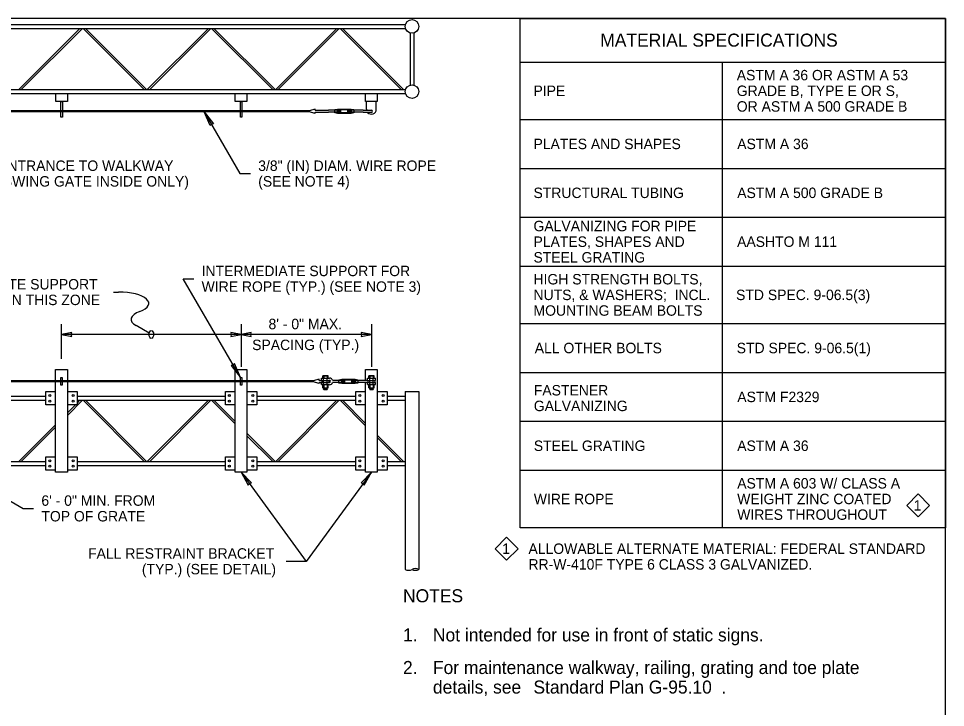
# Model space of a CAD drawing. Extents: x 99862 to 103151, y 100000 to 105076.
# Drawn here: x 101730 to 103151, y 101019 to 102076 of the extents above; entities that cross this region are included whole.
import ezdxf

# ---------------------------------------------------------------- set-up
doc = ezdxf.new("R2010")
doc.units = 0
for name, color, linetype in [('Level 1', 7, 'Continuous'), ('Level 11', 7, 'Continuous'), ('Level 14', 7, 'Continuous'), ('Level 15', 7, 'Continuous'), ('Level 18', 7, 'Continuous'), ('Level 20', 7, 'Continuous'), ('Level 23', 7, 'Continuous'), ('Level 3', 7, 'Continuous'), ('Level 4', 7, 'Continuous'), ('Level 60', 7, 'Continuous'), ('Level 7', 7, 'Continuous')]:
    doc.layers.add(name, color=color, linetype=linetype)

msp = doc.modelspace()

# ---------------------------------------------------------------- linework, layer by layer
at = {"layer": 'Level 1'}
msp.add_lwpolyline([(99862, 99999.5), (103151, 99999.5), (103151, 102075.5), (99862, 102075.5)], close=True, dxfattribs=at)
at = {"layer": 'Level 11'}
for p, q in [((102263.4, 101936.3), (102263.4, 101948.3)), ((102278.3, 101936.3), (102278.3, 101948.3)), ((102167.4, 101934.2), (101540, 101934.2)), ((102167.4, 101932.5), (101540, 101932.5)), ((102175.1, 101934.2), (102167.4, 101934.2)), ((102175.1, 101932.5), (102167.4, 101932.5)), ((102184.4, 101936.7), (102175.1, 101934.2)), ((102175.1, 101934.2), (102175.1, 101932.5)), ((102184.4, 101930), (102175.1, 101932.5)), ((102184.4, 101935), (102184.4, 101936.7)), ((102184.4, 101935), (102205, 101935)), ((102184.4, 101931.7), (102205, 101931.7)), ((102184.4, 101930), (102184.4, 101931.7)), ((102214.8, 101935), (102205, 101935)), ((102214.8, 101931.7), (102205, 101931.7)), ((102219, 101935), (102214.8, 101935)), ((102219, 101931.7), (102214.8, 101931.7)), ((102219, 101935.8), (102239.6, 101935.8)), ((102219, 101930.9), (102219, 101935.8)), ((102219, 101935), (102224, 101935)), ((102219, 101931.7), (102224, 101931.7)), ((102239.6, 101930.9), (102219, 101930.9)), ((102219.8, 101932.5), (102219.8, 101934.2)), ((102220.7, 101931.7), (102220.7, 101935)), ((102221.5, 101932.5), (102221.5, 101934.2)), ((102222.3, 101931.7), (102222.3, 101935)), ((102223.1, 101932.5), (102223.1, 101934.2)), ((102224, 101931.7), (102224, 101935)), ((102239.6, 101935), (102234.6, 101935)), ((102234.6, 101931.7), (102234.6, 101935)), ((102239.6, 101931.7), (102234.6, 101931.7)), ((102235.4, 101932.5), (102235.4, 101934.2)), ((102236.3, 101931.7), (102236.3, 101935)), ((102237.1, 101932.5), (102237.1, 101934.2)), ((102237.9, 101931.7), (102237.9, 101935)), ((102238.8, 101932.5), (102238.8, 101934.2)), ((102239.6, 101935.8), (102239.6, 101930.9)), ((102243.8, 101935), (102239.6, 101935)), ((102243.8, 101931.7), (102239.6, 101931.7)), ((102258.3, 101935), (102243.8, 101935)), ((102258.3, 101931.7), (102243.8, 101931.7)), ((102258.3, 101935), (102270.8, 101935)), ((102258.3, 101931.7), (102270.8, 101931.7))]:
    msp.add_line(p, q, dxfattribs=at)
for points in [[(101794.7, 101948.3), (101797, 101948.3), (101797, 101924.3), (101794.7, 101924.3)], [(102069.8, 101948.3), (102072, 101948.3), (102072, 101924.3), (102069.8, 101924.3)], [(102214.8, 101935.8), (102218.9, 101936.7), (102239.7, 101936.7), (102243.8, 101935.8), (102243.8, 101930.9), (102239.7, 101930), (102218.9, 101930), (102214.8, 101930.9)], [(101794.4, 101525), (101796.7, 101525), (101796.7, 101513), (101794.4, 101513)], [(102069.8, 101525), (102072, 101525), (102072, 101513), (102069.8, 101513)]]:
    msp.add_lwpolyline(points, close=True, dxfattribs=at)
for centre, radius, start, end in [((102270.8, 101936.3), 7.45, 180, 190.3619), ((102270.8, 101936.3), 7.45, 218.7191, 0), ((102270.8, 101933.3), 1.66, 270, 90)]:
    msp.add_arc(centre, radius, start, end, dxfattribs=at)
at = {"layer": 'Level 14'}
msp.add_line((101875.1, 101656), (101883.1, 101656), dxfattribs=at)
for centre, start_param, end_param in [((101883.1, 101638.6), 2.356226, 4.712389), ((101948.7, 101614), 5.497747, 6.859209)]:
    msp.add_ellipse(centre, major_axis=(-46.4, 0), ratio=0.375, start_param=start_param, end_param=end_param, dxfattribs=at)
at = {"layer": 'Level 15'}
for p, q in [((102014.5, 101932.5), (102069.2, 101837.8)), ((102069.2, 101837.8), (102085.2, 101837.8)), ((102069.8, 101525), (101982.3, 101676.4)), ((101982.3, 101676.4), (101998.3, 101676.4)), ((101795.6, 101553.5), (101795.6, 101607)), ((101929.9, 101592.9), (101909.8, 101604.5)), ((102070.9, 101607), (102070.9, 101541.5)), ((102270.8, 101607), (102270.8, 101541.5)), ((102070.9, 101591), (101795.6, 101591)), ((102270.8, 101591), (102070.9, 101591)), ((102070.9, 101380), (102170.9, 101243)), ((102270.8, 101380), (102170.9, 101243)), ((101659.5, 101368.7), (101736.7, 101324.2)), ((101736.7, 101324.2), (101752.7, 101324.2)), ((102170.9, 101243), (102140.2, 101243))]:
    msp.add_line(p, q, dxfattribs=at)
for points in [[(102014.5, 101932.5), (102028.5, 101914.2), (102025.4, 101913.7), (102023.3, 101911.2)], [(101795.6, 101591), (101811.3, 101587.9), (101810.6, 101591), (101811.3, 101594.1)], [(102070.9, 101591), (102055.2, 101594.1), (102055.9, 101591), (102055.2, 101587.9)], [(102070.9, 101591), (102086.6, 101587.9), (102085.9, 101591), (102086.6, 101594.1)], [(102070.9, 101591), (102086.6, 101587.9), (102085.9, 101591), (102086.6, 101594.1)], [(102270.8, 101591), (102255.1, 101594.1), (102255.8, 101591), (102255.1, 101587.9)], [(102069.8, 101525), (102060.9, 101546.3), (102058.9, 101543.8), (102055.8, 101543.3)], [(102070.9, 101380), (102081.9, 101359.8), (102083.7, 101362.4), (102086.8, 101363.3)], [(102270.8, 101380), (102255, 101363.3), (102258, 101362.4), (102259.8, 101359.8)]]:
    msp.add_lwpolyline(points, close=True, dxfattribs=at)
for centre, start, end in [((102327.8, 101239.7), 240, 300), ((102338.2, 101221.7), 60, 120), ((102338.2, 101239.7), 240, 300)]:
    msp.add_arc(centre, 10.4, start, end, dxfattribs=at)
msp.add_ellipse((101933.2, 101591), major_axis=(0, 6), ratio=0.57735, dxfattribs=at)
at = {"layer": 'Level 18'}
for points in [[(101786.6, 101519.8), (101786.6, 101537), (101804.6, 101537), (101804.6, 101519.8)], [(102061.9, 101519.8), (102061.9, 101537), (102079.9, 101537), (102079.9, 101519.8)], [(102279.8, 101537), (102279.8, 101380), (102261.8, 101380), (102261.8, 101517.3)], [(102261.8, 101520.6), (102261.8, 101537), (102279.8, 101537), (102279.8, 101537)], [(101804.6, 101518.2), (101804.6, 101380), (101786.6, 101380), (101786.6, 101518.2)], [(102079.9, 101518.2), (102079.9, 101380), (102061.9, 101380), (102061.9, 101518.2)], [(101786.6, 101482.8), (101771.6, 101482.8), (101771.6, 101503.3), (101786.6, 101503.3)], [(101804.6, 101503.3), (101819.6, 101503.3), (101819.6, 101482.8), (101804.6, 101482.8)], [(102061.9, 101482.8), (102046.9, 101482.8), (102046.9, 101503.3), (102061.9, 101503.3)], [(102079.9, 101503.3), (102094.9, 101503.3), (102094.9, 101482.8), (102079.9, 101482.8)], [(102261.8, 101482.8), (102246.8, 101482.8), (102246.8, 101503.3), (102261.8, 101503.3)], [(102279.8, 101503.3), (102294.8, 101503.3), (102294.8, 101482.8), (102279.8, 101482.8)], [(101786.6, 101382.8), (101771.6, 101382.8), (101771.6, 101403.3), (101786.6, 101403.3)], [(101804.6, 101403.3), (101819.6, 101403.3), (101819.6, 101382.8), (101804.6, 101382.8)], [(102061.9, 101382.8), (102046.9, 101382.8), (102046.9, 101403.3), (102061.9, 101403.3)], [(102079.9, 101403.3), (102094.9, 101403.3), (102094.9, 101382.8), (102079.9, 101382.8)], [(102261.8, 101382.8), (102246.8, 101382.8), (102246.8, 101403.3), (102261.8, 101403.3)], [(102279.8, 101403.3), (102294.8, 101403.3), (102294.8, 101382.8), (102279.8, 101382.8)]]:
    msp.add_lwpolyline(points, dxfattribs=at)
for centre in [(101777.6, 101497.3), (101813.6, 101497.3), (102052.9, 101497.3), (102088.9, 101497.3), (102252.8, 101497.3), (102288.8, 101497.3), (101777.6, 101488.8), (101813.6, 101488.8), (102052.9, 101488.8), (102088.9, 101488.8), (102252.8, 101488.8), (102288.8, 101488.8), (101777.6, 101397.3), (101813.6, 101397.3), (102052.9, 101397.3), (102088.9, 101397.3), (102252.8, 101397.3), (102288.8, 101397.3), (101777.6, 101388.8), (101813.6, 101388.8), (102052.9, 101388.8), (102088.9, 101388.8), (102252.8, 101388.8), (102288.8, 101388.8)]:
    msp.add_circle(centre, 1.5, dxfattribs=at)
at = {"layer": 'Level 20'}
for points in [[(103109.1, 101346.3), (103126.7, 101328.8), (103109.1, 101311.2), (103091.6, 101328.8)], [(102478, 101280), (102495.6, 101262.4), (102478, 101244.9), (102460.5, 101262.4)]]:
    msp.add_lwpolyline(points, close=True, dxfattribs=at)
at = {"layer": 'Level 23'}
for points in [[(101786.8, 101960.3), (101804.8, 101960.3), (101804.8, 101948.3), (101786.8, 101948.3)], [(102061.9, 101960.3), (102079.9, 101960.3), (102079.9, 101948.3), (102061.9, 101948.3)], [(102261.8, 101960.3), (102279.8, 101960.3), (102279.8, 101948.3), (102261.8, 101948.3)]]:
    msp.add_lwpolyline(points, close=True, dxfattribs=at)
at = {"layer": 'Level 3'}
for p, q in [((102498.7, 102008.8), (103151, 102008.8)), ((102808.8, 102008.8), (102808.8, 101294.6)), ((102498.7, 101920.7), (103151, 101920.7)), ((102498.7, 101845.7), (103151, 101845.7)), ((102498.7, 101770.8), (103151, 101770.8)), ((102498.7, 101695.8), (103151, 101695.8)), ((102498.7, 101607.7), (103151, 101607.7)), ((102498.7, 101532.7), (103151, 101532.7)), ((102498.7, 101457.8), (103151, 101457.8)), ((102498.7, 101382.8), (103151, 101382.8))]:
    msp.add_line(p, q, dxfattribs=at)
msp.add_lwpolyline([(102498.7, 102075.5), (103151, 102075.5), (103151, 101294.6), (102498.7, 101294.6)], close=True, dxfattribs=at)
at = {"layer": 'Level 4'}
for p, q in [((102196.2, 101524), (102196.2, 101527.4)), ((102197, 101527.7), (102203.5, 101527.7)), ((102197.9, 101527.4), (102197.9, 101524)), ((102202.7, 101527.4), (102202.7, 101524)), ((102204.4, 101524), (102204.4, 101527.4)), ((102266.7, 101524), (102266.7, 101527.4)), ((102267.6, 101527.7), (102274.1, 101527.7)), ((102268.5, 101527.4), (102268.5, 101524)), ((102273.2, 101527.4), (102273.2, 101524)), ((102274.9, 101524), (102274.9, 101527.4)), ((102173.7, 101519.8), (101534.3, 101519.8)), ((102173.7, 101518.2), (101534.3, 101518.2)), ((102181.4, 101519.8), (102173.7, 101519.8)), ((102181.4, 101518.2), (102173.7, 101518.2)), ((102190.7, 101522.3), (102181.4, 101519.8)), ((102181.4, 101519.8), (102181.4, 101518.2)), ((102190.7, 101515.7), (102181.4, 101518.2)), ((102190.7, 101520.6), (102190.7, 101522.3)), ((102190.7, 101520.6), (102206.5, 101520.6)), ((102190.7, 101517.3), (102206.5, 101517.3)), ((102190.7, 101515.7), (102190.7, 101517.3)), ((102194, 101524), (102206.5, 101524)), ((102194, 101520.6), (102194, 101524)), ((102194, 101514), (102194, 101517.3)), ((102194, 101514), (102206.5, 101514)), ((102196.2, 101514), (102204.4, 101514)), ((102196.2, 101509.2), (102196.2, 101514)), ((102197.5, 101514), (102197.5, 101524)), ((102197.9, 101514), (102197.9, 101509.2)), ((102202.7, 101514), (102202.7, 101509.2)), ((102203, 101514), (102203, 101524)), ((102204.4, 101509.2), (102204.4, 101514)), ((102221, 101520.6), (102211.3, 101520.6)), ((102221, 101517.3), (102211.3, 101517.3)), ((102225.3, 101520.6), (102221, 101520.6)), ((102225.3, 101517.3), (102221, 101517.3)), ((102225.3, 101521.5), (102245.8, 101521.5)), ((102225.3, 101516.5), (102225.3, 101521.5)), ((102225.3, 101520.6), (102230.2, 101520.6)), ((102225.3, 101517.3), (102230.2, 101517.3)), ((102245.8, 101516.5), (102225.3, 101516.5)), ((102226.1, 101518.2), (102226.1, 101519.8)), ((102226.9, 101517.3), (102226.9, 101520.6)), ((102227.8, 101518.2), (102227.8, 101519.8)), ((102228.6, 101517.3), (102228.6, 101520.6)), ((102229.4, 101518.2), (102229.4, 101519.8)), ((102230.2, 101517.3), (102230.2, 101520.6)), ((102245.8, 101520.6), (102240.9, 101520.6)), ((102240.9, 101517.3), (102240.9, 101520.6)), ((102245.8, 101517.3), (102240.9, 101517.3)), ((102241.7, 101518.2), (102241.7, 101519.8)), ((102242.5, 101517.3), (102242.5, 101520.6)), ((102243.4, 101518.2), (102243.4, 101519.8)), ((102244.2, 101517.3), (102244.2, 101520.6)), ((102245, 101518.2), (102245, 101519.8)), ((102245.8, 101521.5), (102245.8, 101516.5)), ((102250.1, 101520.6), (102245.8, 101520.6)), ((102250.1, 101517.3), (102245.8, 101517.3)), ((102264.6, 101520.6), (102250.1, 101520.6)), ((102264.6, 101517.3), (102250.1, 101517.3)), ((102264.6, 101524), (102277.1, 101524)), ((102264.6, 101520.6), (102264.6, 101524)), ((102264.6, 101520.6), (102277.1, 101520.6)), ((102264.6, 101517.3), (102277.1, 101517.3)), ((102264.6, 101514), (102264.6, 101517.3)), ((102264.6, 101514), (102277.1, 101514)), ((102266.7, 101514), (102274.9, 101514)), ((102266.7, 101509.2), (102266.7, 101514)), ((102268.1, 101514), (102268.1, 101524)), ((102268.5, 101514), (102268.5, 101509.2)), ((102273.2, 101514), (102273.2, 101509.2)), ((102273.6, 101514), (102273.6, 101524)), ((102274.9, 101509.2), (102274.9, 101514)), ((102277.1, 101520.6), (102277.1, 101524)), ((102277.1, 101514), (102277.1, 101517.3)), ((102197, 101508.9), (102203.5, 101508.9)), ((102197.5, 101506.9), (102197.5, 101508.9)), ((102197.5, 101507.9), (102203, 101507.9)), ((102197.5, 101506.9), (102203, 101506.9)), ((102197.5, 101506.9), (102197.8, 101506.4)), ((102197.8, 101506.4), (102202.7, 101506.4)), ((102198.4, 101508.4), (102202.2, 101508.4)), ((102198.4, 101507.4), (102202.2, 101507.4)), ((102203, 101506.9), (102202.7, 101506.4)), ((102203, 101506.9), (102203, 101508.9)), ((102267.6, 101508.9), (102274.1, 101508.9)), ((102268.1, 101506.9), (102268.1, 101508.9)), ((102268.1, 101507.9), (102273.6, 101507.9)), ((102268.1, 101506.9), (102273.6, 101506.9)), ((102268.1, 101506.9), (102268.4, 101506.4)), ((102268.4, 101506.4), (102273.3, 101506.4)), ((102268.9, 101508.4), (102272.7, 101508.4)), ((102268.9, 101507.4), (102272.7, 101507.4)), ((102273.6, 101506.9), (102273.3, 101506.4)), ((102273.6, 101506.9), (102273.6, 101508.9))]:
    msp.add_line(p, q, dxfattribs=at)
msp.add_lwpolyline([(102221, 101521.5), (102225.2, 101522.3), (102245.9, 101522.3), (102250.1, 101521.5), (102250.1, 101516.5), (102245.9, 101515.7), (102225.2, 101515.7), (102221, 101516.5)], close=True, dxfattribs=at)
for centre, radius, start, end in [((102197, 101526.2), 1.5, 54.7199, 125.2801), ((102200.3, 101517.3), 10.3, 76.7504, 103.2496), ((102203.5, 101526.2), 1.5, 54.7199, 125.2801), ((102267.6, 101526.2), 1.5, 54.7199, 125.2801), ((102270.8, 101517.3), 10.3, 76.7504, 103.2496), ((102274.1, 101526.2), 1.5, 54.7199, 125.2801), ((102196.9, 101519), 2.22, 131.7358, 228.2642), ((102203.7, 101519), 2.22, 311.7358, 47.4328), ((102206.5, 101519), 5.03, 19.2502, 90), ((102206.5, 101519), 1.66, 270, 90), ((102206.5, 101519), 5.03, 270, 340.7483), ((102267.4, 101519), 2.22, 131.7358, 228.2642), ((102274.2, 101519), 2.22, 311.7358, 48.2642), ((102197, 101510.4), 1.5, 234.7199, 305.2801), ((102200.3, 101519.2), 10.3, 256.7504, 283.2496), ((102203.5, 101510.4), 1.5, 234.7199, 305.2801), ((102267.6, 101510.4), 1.5, 234.7199, 305.2801), ((102270.8, 101519.2), 10.3, 256.7504, 283.2496), ((102274.1, 101510.4), 1.5, 234.7199, 305.2801)]:
    msp.add_arc(centre, radius, start, end, dxfattribs=at)
at = {"layer": 'Level 60'}
msp.add_line((103151, 102075.5), (103151, 102075.5), dxfattribs=at)
at = {"layer": 'Level 7'}
for p, q in [((100622.1, 102066.6), (102322.6, 102066.6)), ((100622.1, 102060.3), (102322.6, 102060.3)), ((101823.9, 102060.3), (101730.2, 101966.6)), ((101827.6, 102060.3), (101733.9, 101966.6)), ((101828.7, 102060.3), (101922.4, 101966.6)), ((101832.3, 102060.3), (101926.1, 101966.6)), ((102020.9, 102060.3), (101927.1, 101966.6)), ((102024.6, 102060.3), (101930.8, 101966.6)), ((102025.6, 102060.3), (102119.4, 101966.6)), ((102029.3, 102060.3), (102123, 101966.6)), ((102217.8, 102060.3), (102124.1, 101966.6)), ((102221.5, 102060.3), (102127.8, 101966.6)), ((102222.6, 102060.3), (102316.3, 101966.6)), ((102226.2, 102060.3), (102320, 101966.6)), ((102330.4, 102053.4), (102330.4, 101973.5)), ((102335.6, 102053.4), (102335.6, 101973.5)), ((100622.1, 101966.6), (102322.6, 101966.6)), ((100622.1, 101960.3), (102322.6, 101960.3)), ((102322.6, 101503.5), (102322.6, 101230.7)), ((102322.6, 101503.5), (102343.4, 101503.5)), ((102343.4, 101503.5), (102343.4, 101230.7)), ((101563, 101496.2), (101771.6, 101496.2)), ((101563, 101490), (101771.6, 101490)), ((101827.6, 101490), (101804.6, 101466.9)), ((101819.6, 101496.2), (102046.9, 101496.2)), ((101819.6, 101490), (102046.9, 101490)), ((101823.9, 101490), (101819.6, 101485.6)), ((101828.7, 101490), (101922.4, 101396.2)), ((101832.3, 101490), (101926.1, 101396.2)), ((102020.9, 101490), (101927.1, 101396.2)), ((102024.6, 101490), (101930.8, 101396.2)), ((102025.6, 101490), (102061.9, 101453.7)), ((102029.3, 101490), (102061.9, 101457.4)), ((102094.9, 101496.2), (102246.8, 101496.2)), ((102094.9, 101490), (102246.8, 101490)), ((102217.8, 101490), (102124.1, 101396.2)), ((102221.5, 101490), (102127.8, 101396.2)), ((102222.6, 101490), (102261.8, 101450.7)), ((102226.2, 101490), (102261.8, 101454.4)), ((102294.8, 101496.2), (102322.6, 101496.2)), ((102294.8, 101490), (102322.6, 101490)), ((101816.8, 101482.8), (101804.6, 101470.6)), ((101786.6, 101452.6), (101730.2, 101396.2)), ((101786.6, 101448.9), (101733.9, 101396.2)), ((102079.9, 101439.4), (102123, 101396.2)), ((102079.9, 101435.7), (102119.4, 101396.2)), ((102279.8, 101436.4), (102320, 101396.2)), ((102279.8, 101432.7), (102316.3, 101396.2)), ((101563, 101396.2), (101771.6, 101396.2)), ((101563, 101390), (101771.6, 101390)), ((101819.6, 101396.2), (102046.9, 101396.2)), ((101819.6, 101390), (102046.9, 101390)), ((102094.9, 101396.2), (102246.8, 101396.2)), ((102094.9, 101390), (102246.8, 101390)), ((102294.8, 101396.2), (102322.6, 101396.2)), ((102294.8, 101390), (102322.6, 101390))]:
    msp.add_line(p, q, dxfattribs=at)
for centre in [(102333, 102063.4), (102333, 101963.4)]:
    msp.add_circle(centre, 10.4, dxfattribs=at)

# ---------------------------------------------------------------- texts
at = {"layer": 'Level 20'}
for s, height, p in [('MATERIAL SPECIFICATIONS', 20, (102621.7, 102032.4)), ('ASTM A 36 OR ASTM A 53', 16, (102831, 101980.7)), ('PIPE', 16, (102519.3, 101956.7)), ('GRADE B, TYPE E OR S,', 16, (102831, 101956.7)), ('OR ASTM A 500 GRADE B', 16, (102831, 101932.7)), ('PLATES AND SHAPES', 16, (102519.3, 101875.2)), ('ASTM A 36', 16, (102831.7, 101875.2)), ('ENTRANCE TO WALKWAY', 16, (101698.5, 101841.8)), ('3/8" (IN) DIAM. WIRE ROPE', 16, (102097.2, 101841.8)), ('(SWING GATE INSIDE ONLY)', 16, (101698.5, 101817.8)), ('(SEE NOTE 4)', 16, (102097.2, 101817.8)), ('STRUCTURAL TUBING', 16, (102519.3, 101800.2)), ('ASTM A 500 GRADE B', 16, (102831.7, 101800.2)), ('GALVANIZING FOR PIPE', 16, (102519.3, 101749.3)), ('PLATES, SHAPES AND', 16, (102519.3, 101725.3)), ('AASHTO M 111', 16, (102831.5, 101725.3)), ('STEEL GRATING', 16, (102519.3, 101701.3)), ('INTERMEDIATE SUPPORT FOR', 16, (102010.4, 101680.4)), ('HIGH STRENGTH BOLTS,', 16, (102519.3, 101667.7)), ('SAFETY CABLE AND INTERMEDIATE SUPPORT', 16, (101365.9, 101660)), ('WIRE ROPE (TYP.) (SEE NOTE 3)', 16, (102010.4, 101656.4)), ('NUTS, & WASHERS;  INCL.', 16, (102519.3, 101643.7)), ('STD SPEC. 9-06.5(3)', 16, (102829.9, 101643.7)), ('ARE OPTIONAL IN THIS ZONE', 16, (101549.2, 101636)), ('MOUNTING BEAM BOLTS', 16, (102519.3, 101619.7)), ('8\' - 0" MAX.', 16, (102113, 101599)), ('SPACING (TYP.)', 16, (102087.9, 101567)), ('ALL OTHER BOLTS', 16, (102521.2, 101562.2)), ('STD SPEC. 9-06.5(1)', 16, (102830.9, 101562.2)), ('FASTENER', 16, (102519.8, 101497.4)), ('ASTM F2329', 16, (102831.8, 101487.2)), ('GALVANIZING', 16, (102519.8, 101473.4)), ('STEEL GRATING', 16, (102519.8, 101412.3)), ('ASTM A 36', 16, (102831.7, 101412.3)), ('ASTM A 603 W/ CLASS A', 16, (102831.7, 101354.7)), ('6\' - 0" MIN. FROM', 16, (101764.7, 101328.2)), ('WIRE ROPE', 16, (102519.8, 101330.7)), ('WEIGHT ZINC COATED', 16, (102831.7, 101330.7)), ('1', 16, (103102.3, 101320.8)), ('TOP OF GRATE', 16, (101764.7, 101304.2)), ('WIRES THROUGHOUT', 16, (102831.7, 101306.7)), ('1', 16, (102471.2, 101254.4)), ('ALLOWABLE ALTERNATE MATERIAL: FEDERAL STANDARD', 16, (102511.6, 101254.4)), ('FALL RESTRAINT BRACKET', 16, (101836.3, 101247.1)), ('RR-W-410F TYPE 6 CLASS 3 GALVANIZED.', 16, (102511.6, 101230.4)), ('(TYP.) (SEE DETAIL)', 16, (101918.8, 101223.1)), ('NOTES', 20, (102319.2, 101180.2)), ('1.', 20, (102319.2, 101120.2)), ('Not intended for use in front of static signs.', 20, (102365.1, 101120.2)), ('2.', 20, (102319.2, 101070.2)), ('For maintenance walkway, railing, grating and toe plate', 20, (102365.1, 101070.2)), ('details, see ', 20, (102365.1, 101040.2)), ('Standard Plan G-95.10', 20, (102519.2, 101040.2)), ('.', 20, (102807.5, 101040.2))]:
    msp.add_text(s, height=height, dxfattribs=at).set_placement(p)

doc.saveas('drawing.dxf')
